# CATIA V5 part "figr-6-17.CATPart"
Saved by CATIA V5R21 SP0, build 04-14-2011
Part number: Part1
Bounding box of the stored display mesh (mm): x 0 to 150, y -70 to 70, z -150 to 69.804
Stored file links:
  D:\CATIA V5R21 E-RESOURCES\CATIA-V5R21\catia-v5r21-prt\c06-catia-v5r21-prt\c06-catia-v5r21-figr-6-17.CATPart
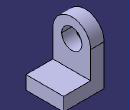
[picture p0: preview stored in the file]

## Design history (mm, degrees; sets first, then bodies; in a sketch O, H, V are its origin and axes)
Body1 (main body)
  Sketch1 on yz-plane, origin (0, 0, 0), H (0, 1, 0), V (0, 0, 1)
    arc A1 centre (0, 0) radius 70 from (70, 0) to (-70, 0) ccw
    point P1 (70, 0)
    point P2 (-70, 0)
    line L1 (-70, 0) -> (-70, -150)
    line L2 (-70, -150) -> (70, -150)
    line L3 (70, -150) -> (70, 0)
    circle A2 centre (0, 0) radius 37.5
    radius A1 = 70
    radius A2 = 37.5
    distance O L2 = 150
    coincidence: P1 H, P2 H
    tangency: L1 A1, L3 A1
    horizontal: L2 H
  Pad1: profile Sketch1, direction (1, 0, 0), length 50
  Sketch2 on face of Pad1, origin (50, 0, 0), H (0, 1, 0), V (0, 0, 1)
    line L1 (-70, -150) -> (70, -150)
    line L2 (70, -150) -> (70, -100)
    line L3 (70, -100) -> (-70, -100)
    line L4 (-70, -100) -> (-70, -150)
    reference projected line E1 (-70, -150) -> (70, -150) from edge [face of Pad1 | face of Pad1]
    reference projected line E2 (-70, 0) -> (-70, -150) from edge [face of Pad1 | face of Pad1]
    reference projected line E3 (70, -150) -> (70, 0) from edge [face of Pad1 | face of Pad1]
    length L2 = 50
    horizontal: L1 H, L3 H
    vertical: L2 V, L4 V
    coincidence: L1 E1, E2 L4, L2 E3
  Pad2: profile Sketch2, direction (1, 0, 0), length 100
  Sketch3 on face of Pad1, origin (50, 0, 0), H (0, 1, 0), V (0, 0, 1)
    point P1 (45.5554, 53.148)
    reference projected arc E1 centre (0, 0) radius 70 from (70, 0) to (-70, 0) ccw from edge [face of Pad1 | face of Pad1]
    coincidence: P1 E1
  Sketch4 on face of Pad2, origin (0, 0, -100), H (1, 0, 0), V (0, 1, 0)
    point P1 (110, 20)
